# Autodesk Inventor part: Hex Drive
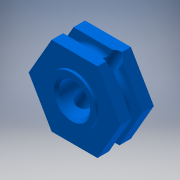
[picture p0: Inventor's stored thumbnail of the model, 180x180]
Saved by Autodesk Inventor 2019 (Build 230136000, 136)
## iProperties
Shininess: 41.0
Compacted: True
Length Units: 11272
Angle Units: 11279
Time Units: 11290
Mass Units: 11286
Length Display Precision: 4
Angle Display Precision: 2
Company: Autodesk
Created: 2000-05
Part Number: Hex Drive
Project: Inventor Samples
User Status: IN PROGRESS
Document SubType Name: Modeling
Designer: Autodesk, Inc.
Density: 1.13 g/cm^3
Material: Nylon-6/6
Mass: 0.50205 g
Surface Area: 6.13121 cm^2
Volume: 0.444292 cm^3
Appearance: Electric Blue
Density: 0.0
Volumn: 0.0
Area: 0.0
PropertySet Name: Model Information
Control State: 0
Master: False
Checked Out: False
Checked Out Date: 2018-05-30
Last Check In Date: 2018-05-30
Author: Autodesk, Inc.
Revision Number: A
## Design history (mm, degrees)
node "Extrusion1" dims "d1" = 5.08, "d2" = 0
  sketch "Sketch2"
    geometry: L1 (6.966, 0)-(3.483, -6.032); L2 (3.483, -6.032)-(-3.483, -6.032); L3 (-3.483, -6.032)-(-6.966, 0); L4 (-6.966, 0)-(-3.483, 6.032); L5 (-3.483, 6.032)-(3.483, 6.032); L6 (3.483, 6.032)-(6.966, 0); C1 r 6.032 at (0, 0)
    constraints: 12 end point, 6 tangent, 4 equal length, 1 centre point, 1 horizontal, 1 parallel, 1 other
    dimensions: "d0" = 12.065 diameter of C1
node "Extrusion2" dims "d5" = 0.381, "d6" = 0
  sketch "Sketch3"
    geometry: C1 r 6.032 at (0, 0) reference; C2 r 3.651 at (0, 0); C3 r 2.381 at (0, 0)
    constraints: 2 centre point, 2 coincident
    dimensions: "d3" = 4.7625 diameter of C3; "d4" = 1.27 radial gap between concentric circles of C2 C3
node "Extrusion3" dims "d7" = 0.381, "d8" = 0
  sketch "Sketch4"
    geometry: C1 r 2.381 at (0, 0) reference
node "Chamfer1" dims "d9" = 0.381, "d10" = 0.381, "d19" = 45 deg
workaxis "Work Axis1"
workplane "Work Plane1"
workplane "Work Plane2"
node "Extrusion4" dims "d13" = 0.381, "d14" = 0
  sketch "Sketch5"
    geometry: L1 (0, 0)-(0, 5.08) reference; C1 r 1.191 at (0, 2.54)
    constraints: 1 centre point, 1 midpoint
    dimensions: "d12" = 2.38125 diameter of C1
workaxis "Work Axis2"
node "Revolution1" dims "d17" = 90 deg
  sketch "Sketch6"
    geometry: L1 (-12.19, -2.54)-(12.19, -2.54) reference; L2 (-6.966, -6.172)-(-6.966, 1.473) reference; L3 (-5.378, -3.334)-(-6.966, -3.334); L4 (-5.378, -1.746)-(-6.966, -1.746); L5 (0, -6.172)-(0, 1.473) reference; A1 r 0.794 centre (-5.378, -2.54) between (-5.378, -3.334) and (-5.378, -1.746)
    constraints: 4 end point, 3 point on line, 2 perpendicular, 2 point on circle, 2 tangent, 1 centre point
    dimensions: "d16" = 1.5875 diameter of A1; "d18" = 1.5875 distance from line of L2 A1.centre
body "Solid1"
other parameters: "d11" = 90 deg, "d15" = 90 deg
